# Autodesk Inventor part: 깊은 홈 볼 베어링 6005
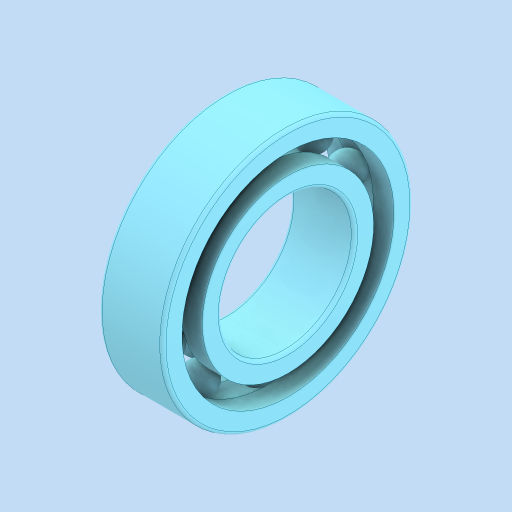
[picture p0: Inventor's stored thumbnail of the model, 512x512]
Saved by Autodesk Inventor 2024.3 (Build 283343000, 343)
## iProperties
Created: 2025-11
Part Number: 깊은 홈 볼 베어링 6005
Material: 강철, 연강
Description: 깊은 그루브 볼 베어링
Document SubType Name: Modeling
Designer: PC2-03
Density: 7.85 g/cm^3
Appearance: 기본값
Author: jhkim
Sending System: Autodesk Inventor 2026
Preprocessor: ST-DEVELOPER v20.1
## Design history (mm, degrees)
feature "Solid1"
feature "Solid1:1"
feature "Solid1:2"
feature "Solid1:3"
feature "Solid1:4"
feature "Solid1:5"
feature "Solid1:6"
feature "Solid1:7"
feature "Solid1:8"
feature "Solid1:9"
feature "Solid1:10"
feature "Solid1:11"
node "솔리드1"
node "솔리드2"
node "솔리드3"
node "솔리드4"
node "솔리드5"
node "솔리드6"
node "솔리드7"
node "솔리드8"
node "솔리드9"
node "솔리드10"
node "솔리드11"
node "솔리드12"
